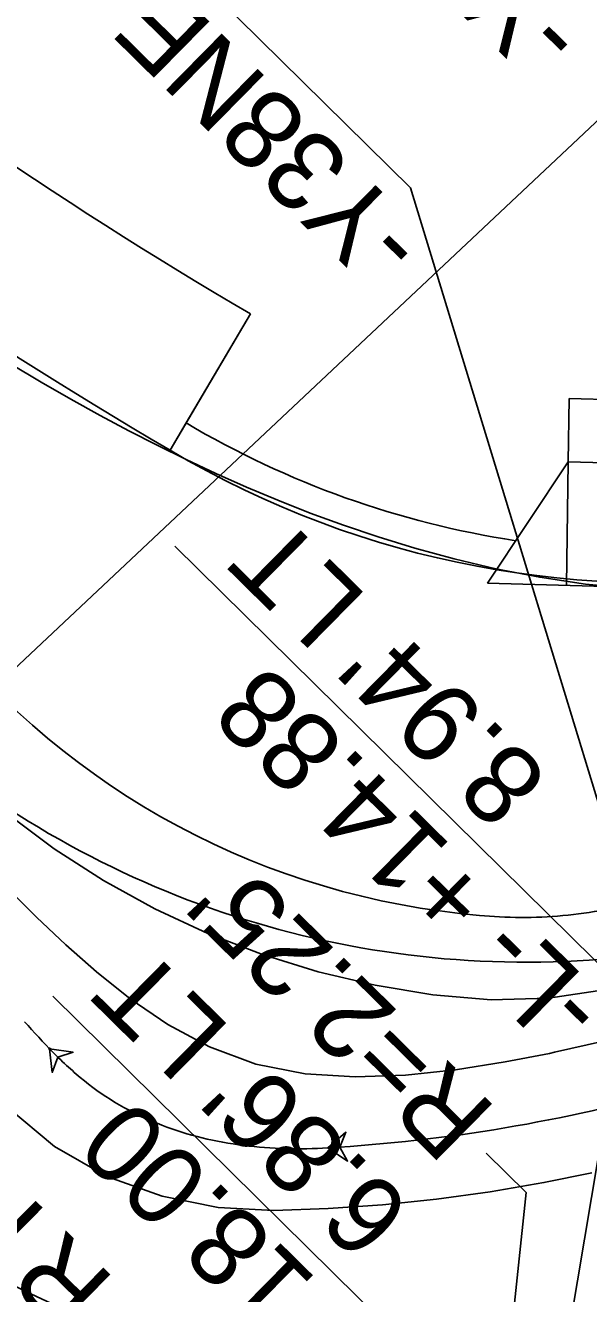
# Model space of a CAD drawing. Extents: x 1262642 to 1268358, y 767825 to 773481.
# Drawn here: x 1266759.8 to 1266795.4, y 772205.7 to 772285.8 of the extents above; entities that cross this region are included whole.
import ezdxf

# ---------------------------------------------------------------- set-up
doc = ezdxf.new("R2010")
doc.units = 0
for name, color, linetype in [('Old_Level_20', 7, 'Continuous'), ('Prop Conc 2ft 6in Curb and Gutter', 7, 'Continuous'), ('Prop Dimension', 7, 'Continuous'), ('Prop Dimension Text', 7, 'Continuous'), ('Prop EOT', 7, 'Continuous'), ('Prop Horizontal Alignment', 7, 'Continuous'), ('Prop Horizontal Alignment Station Label', 7, 'Continuous'), ('Prop Lane Lines', 7, 'Continuous'), ('Prop Paved Shoulder', 7, 'Continuous'), ('Prop Shade Light', 7, 'Continuous'), ('Scratch_Level_3', 7, 'Continuous')]:
    doc.layers.add(name, color=color, linetype=linetype)

msp = doc.modelspace()

# ---------------------------------------------------------------- linework, layer by layer
at = {"layer": 'Old_Level_20'}
for p, q in [((1266794.066, 772258.223), (1266794.127, 772262.222)), ((1266794.127, 772262.222), (1266798.126, 772262.116)), ((1266788.957, 772250.576), (1266794.066, 772258.223)), ((1266794.066, 772258.223), (1266793.948, 772250.424)), ((1266798.065, 772258.117), (1266794.066, 772258.223)), ((1266797.947, 772250.302), (1266788.957, 772250.576))]:
    msp.add_line(p, q, dxfattribs=at)
at = {"layer": 'Prop Conc 2ft 6in Curb and Gutter'}
msp.add_line((1266769.917, 772260.681), (1266768.898, 772258.96), dxfattribs=at)
msp.add_arc((1266799.465, 772310.59), 58, 239.37252, 261.35139, dxfattribs=at)
at = {"layer": 'Prop Dimension'}
msp.add_line((1266803.354, 772212.453), (1266784.103, 772275.524), dxfattribs=at)
at = {"layer": 'Prop Dimension Text'}
for p, q in [((1266743.586, 772315.446), (1266784.103, 772275.524)), ((1266769.21, 772252.901), (1266797.725, 772224.805)), ((1266761.492, 772224.482), (1266788.074, 772198.292)), ((1266788.878, 772214.575), (1266791.406, 772212.084))]:
    msp.add_line(p, q, dxfattribs=at)
for points in [[(1266797.725, 772224.805), (1266789.373, 772175.059)], [(1266791.406, 772212.084), (1266787.561, 772175.561)]]:
    msp.add_lwpolyline(points, dxfattribs=at)
at = {"layer": 'Prop EOT'}
for centre, radius, start, end in [((1266920.515, 772517.827), 300, 222.71603, 239.6427), ((1266799.465, 772310.59), 60, 239.37252, 317.90382)]:
    msp.add_arc(centre, radius, start, end, dxfattribs=at)
at = {"layer": 'Prop Horizontal Alignment'}
msp.add_arc((1275047.307, 780021.225), 11400, 222.9935866, 225.4043192, dxfattribs=at)
at = {"layer": 'Prop Horizontal Alignment Station Label'}
msp.add_line((1266683.114, 772173.743), (1266860.999, 772340.982), dxfattribs=at)
at = {"layer": 'Prop Lane Lines'}
for centre, radius, start, end in [((1275047.307, 780021.225), 11427, 216.3674993, 223.5476842), ((1266791.4, 772286.629), 60, 223.13275, 315.73419), ((1275047.307, 780021.225), 11427, 222.9935866, 225.3637298)]:
    msp.add_arc(centre, radius, start, end, dxfattribs=at)
at = {"layer": 'Prop Paved Shoulder'}
msp.add_line((1266769.917, 772260.681), (1266773.992, 772267.565), dxfattribs=at)
msp.add_arc((1266920.515, 772517.827), 290, 222.71603, 239.65201, dxfattribs=at)
at = {"layer": 'Prop Shade Light'}
msp.add_line((1266773.992, 772267.565), (1266768.898, 772258.96), dxfattribs=at)
for radius, end in [(290, 239.65201), (300, 239.6427)]:
    msp.add_arc((1266920.515, 772517.827), radius, 222.71603, end, dxfattribs=at)
at = {"layer": 'Scratch_Level_3'}
for points in [[(1266798.144, 772250.227), (1266795.159, 772250.511), (1266792.263, 772250.936), (1266789.482, 772251.473), (1266786.847, 772252.093), (1266784.374, 772252.768), (1266782.045, 772253.484), (1266779.866, 772254.221), (1266777.761, 772254.994), (1266775.715, 772255.801), (1266773.727, 772256.636), (1266771.794, 772257.496), (1266769.914, 772258.377), (1266768.085, 772259.275), (1266766.289, 772260.195), (1266764.484, 772261.159), (1266762.632, 772262.184), (1266760.749, 772263.266), (1266758.826, 772264.41), (1266756.843, 772265.63), (1266754.753, 772266.958)], [(1266796.344, 772224.878), (1266792.813, 772224.356), (1266789.186, 772224.25), (1266785.516, 772224.574), (1266781.868, 772225.177), (1266778.27, 772226.026), (1266774.738, 772227.117), (1266771.287, 772228.446), (1266767.935, 772230.007), (1266764.697, 772231.792), (1266761.587, 772233.794), (1266758.621, 772236.002), (1266755.811, 772238.406), (1266753.171, 772240.996), (1266750.714, 772243.76), (1266748.433, 772246.659), (1266746.21, 772249.534)], [(1266792.886, 772220.875), (1266790.075, 772220.339), (1266786.935, 772219.843), (1266783.775, 772219.498), (1266780.6, 772219.381), (1266777.432, 772219.582), (1266774.318, 772220.201), (1266771.398, 772221.283), (1266768.757, 772222.703), (1266766.385, 772224.315), (1266764.252, 772226.012), (1266762.322, 772227.719), (1266760.466, 772229.481), (1266758.549, 772231.381)], [(1266796.365, 772229.941), (1266796.037, 772229.882), (1266795.708, 772229.826), (1266795.379, 772229.775), (1266795.049, 772229.727), (1266794.718, 772229.683), (1266794.388, 772229.642), (1266794.056, 772229.606), (1266793.724, 772229.573), (1266793.392, 772229.545), (1266793.06, 772229.52), (1266792.727, 772229.5), (1266792.394, 772229.483), (1266792.061, 772229.47), (1266791.728, 772229.462), (1266791.395, 772229.458), (1266791.061, 772229.458), (1266790.728, 772229.462), (1266790.395, 772229.47), (1266790.062, 772229.483), (1266789.729, 772229.5)], [(1266810.439, 772226.223), (1266808.442, 772225.431), (1266805.472, 772224.344), (1266802.442, 772223.344), (1266799.381, 772222.442), (1266796.299, 772221.64), (1266793.197, 772220.939), (1266792.886, 772220.875)], [(1266761.287, 772221.163), (1266761.056, 772221.404), (1266760.827, 772221.646), (1266760.599, 772221.889), (1266760.373, 772222.134), (1266760.148, 772222.38), (1266759.924, 772222.627), (1266759.702, 772222.875)], [(1266778.876, 772214.91), (1266778.543, 772214.891), (1266778.21, 772214.876), (1266777.877, 772214.864), (1266777.543, 772214.855), (1266777.21, 772214.851), (1266776.877, 772214.849), (1266776.544, 772214.852), (1266776.21, 772214.859), (1266775.877, 772214.869), (1266775.544, 772214.884), (1266775.211, 772214.902), (1266774.879, 772214.925), (1266774.546, 772214.952), (1266774.215, 772214.983), (1266773.883, 772215.018), (1266773.552, 772215.058), (1266773.222, 772215.102), (1266772.892, 772215.151), (1266772.563, 772215.204), (1266772.235, 772215.262), (1266771.907, 772215.325), (1266771.581, 772215.392), (1266771.255, 772215.464), (1266770.931, 772215.541), (1266770.608, 772215.623), (1266770.286, 772215.71), (1266769.966, 772215.802), (1266769.647, 772215.898), (1266769.329, 772216), (1266769.014, 772216.107), (1266768.7, 772216.219), (1266768.388, 772216.336), (1266768.077, 772216.459), (1266767.77, 772216.586), (1266767.464, 772216.719), (1266767.16, 772216.857), (1266766.86, 772217.001), (1266766.561, 772217.149), (1266766.266, 772217.303), (1266765.973, 772217.463), (1266765.683, 772217.627), (1266765.396, 772217.797), (1266765.113, 772217.973), (1266764.833, 772218.153), (1266764.556, 772218.339), (1266764.283, 772218.53), (1266764.014, 772218.727), (1266763.748, 772218.928), (1266763.487, 772219.135), (1266763.23, 772219.348)], [(1266795.555, 772213.322), (1266792.526, 772212.711), (1266789.141, 772212.136), (1266785.738, 772211.67), (1266782.323, 772211.314), (1266778.897, 772211.069), (1266775.456, 772210.941), (1266771.942, 772211.148), (1266768.398, 772211.847), (1266764.912, 772213.108), (1266761.603, 772214.984), (1266758.62, 772217.483)], [(1266758.054, 772206.709), (1266759.789, 772205.836), (1266762.724, 772204.476), (1266765.71, 772203.241), (1266768.74, 772202.14), (1266771.799, 772201.18), (1266774.867, 772200.369), (1266777.932, 772199.711), (1266780.996, 772199.204), (1266783.988, 772198.853), (1266786.887, 772198.651), (1266789.688, 772198.586), (1266792.42, 772198.647), (1266795.121, 772198.831), (1266797.787, 772199.135), (1266800.414, 772199.559), (1266803.004, 772200.1), (1266805.549, 772200.756), (1266808.059, 772201.531), (1266810.499, 772202.411), (1266812.883, 772203.399), (1266815.228, 772204.498), (1266815.459, 772204.613)]]:
    msp.add_lwpolyline(points, dxfattribs=at)
for points in [[(1266761.287, 772221.163), (1266761.454, 772219.672), (1266761.807, 772220.623), (1266762.77, 772220.939)], [(1266778.876, 772214.91), (1266780.116, 772214.067), (1266779.624, 772214.953), (1266780.011, 772215.89)]]:
    msp.add_lwpolyline(points, close=True, dxfattribs=at)
msp.add_circle((1266761.287, 772221.163), 0.0417, dxfattribs=at)
msp.add_circle((1266761.287, 772221.163), 0.0417, dxfattribs=at)
for centre, radius, start, end in [((1266792.555, 772278.491), 49.072, 219.92261, 266.69799), ((1266779.464, 772238.672), 25.239, 223.9276, 229.96723), ((1266773.012, 772317.337), 102.595, 273.27619, 285.84978), ((1266882.309, 772367.05), 212.577, 228.35539, 237.4405)]:
    msp.add_arc(centre, radius, start, end, dxfattribs=at)

# ---------------------------------------------------------------- texts
at = {"layer": 'Prop Dimension'}
msp.add_text("R=2.25'", height=5, rotation=135.42387, dxfattribs=at).set_placement((1266789.638, 772217.303))
at = {"layer": 'Prop Dimension Text'}
for s, p in [('-Y38NE- +04.43', (1266795.378, 772285.545)), ('-Y38NE- +84.08', (1266785.276, 772272.357)), ("8.94' LT", (1266792.986, 772238.312)), ('-L- +14.88', (1266796.722, 772224.101)), ("6.86' LT", (1266784.343, 772211.075)), ('-L- +18.00', (1266788.22, 772196.725)), ("10.25' RT", (1266779.672, 772192.586))]:
    msp.add_text(s, height=5, rotation=135.42387, dxfattribs=at).set_placement(p)

doc.saveas('drawing.dxf')
